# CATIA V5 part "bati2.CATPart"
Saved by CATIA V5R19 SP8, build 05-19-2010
Part number: Pièce4
Bounding box of the stored display mesh (mm): x -21 to 21, y -5 to 25, z -65 to 4.74
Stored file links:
  G:\IAO\IAO_2010\iao\IAO_MMS_Groupe3\PB\cgourmelen\Projet_IAO_gourmelen_camille\Projet_IAO_gourmelen_camille\bati2.CATPart
  G:\IAO\IAO_2010\iao\IAO_MMS_Groupe3\PB\cgourmelen\Projet_IAO_gourmelen_camille\Projet_IAO_gourmelen_camille\Catia_Gourmelen\squelette total.CATProduct
  G:\IAO\IAO_2010\iao\IAO_MMS_Groupe3\PB\cgourmelen\Projet_IAO_gourmelen_camille\Projet_IAO_gourmelen_camille\Part7.CATPart
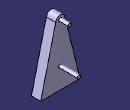
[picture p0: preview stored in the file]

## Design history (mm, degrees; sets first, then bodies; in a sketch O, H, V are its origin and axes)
Body1 (main body)
  Sketch1 on zx-plane, origin (0, 0, 0), H (-1, 0, 0), V (0, 0, 1)
    line L1 (-5, 0) -> (-21, -65)
    point P1 (-5, 0)
    point P2 (-21, -65)
    line L2 (-21, -65) -> (0, -65)
    point P3 (0, -65)
    point P4 (21, -65)
    point P5 (5, 0)
    line L3 (5, 0) -> (21, -65)
    point P6 (0, -65)
    line L4 (21, -65) -> (0, -65)
    arc A1 centre (0, -0.2676) radius 5.0072 from (-5, 0) to (5, 0) cw
    point P8 (0, 4.7396)
    distance P1 L2 = 65
    length L2 = 21
    distance P1 O = 5
    coincidence: P1 H, P3 V, A1 P8, P8 V, P3 P6
    horizontal: L2 H
    symmetry: P2 P4 V, P1 P5 V, L1 L3 V, P3 P6 V, L2 L4 V
  Pad1: profile Sketch1, direction (0, 1, 0), length 5, mirrored extent
  Sketch2 on zx-plane, origin (0, 0, 0), H (-1, 0, 0), V (0, 0, 1)
    circle A1 centre (0, 0) radius 2
    point P1 (2, 0)
    radius A1 = 2
    coincidence: A1 P1, P1 H
  Pad2: profile Sketch2, direction (0, 1, 0), length 15
  Line1: stored without definition
  Sketch3 on end face of Pad1, origin (0, 5, 0), H (-1, 0, 0), V (0, 0, 1)
    circle A1 centre (0, -43) radius 2
    point P1 (0, -43)
    reference projected point E1 (0, -43) from Point1
    radius A1 = 2
    coincidence: P1 V, E1 P1
  Pad3: profile Sketch3, direction (0, 1, 0), length 20
  Point1: stored without definition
